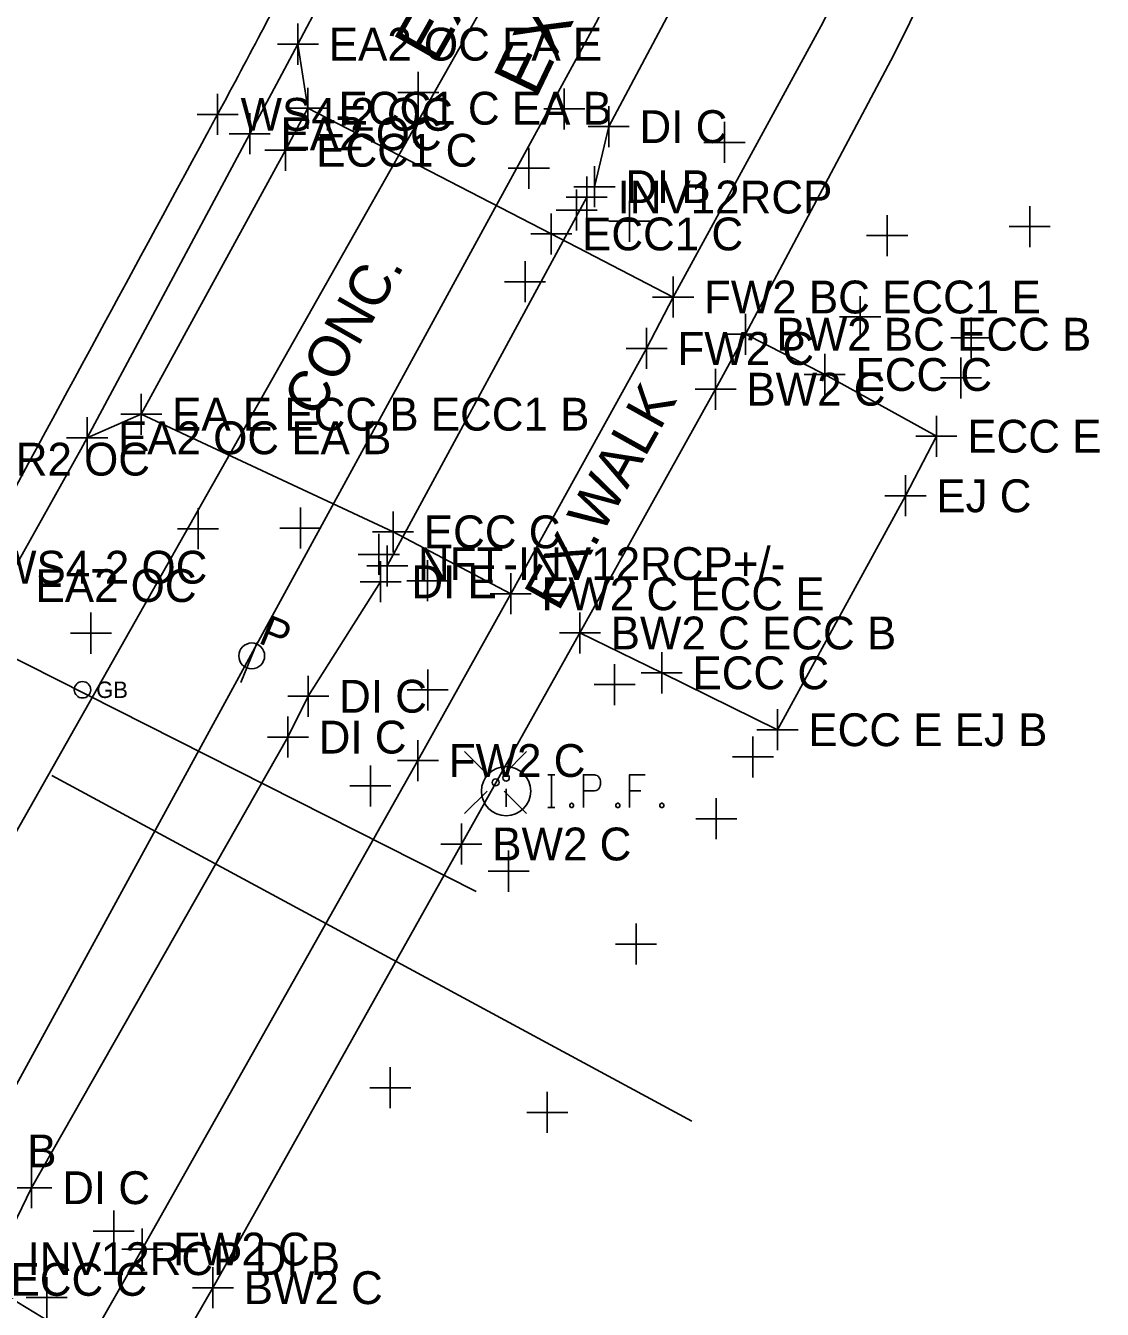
# Model space of a CAD drawing. Extents: x 1363693 to 1365209, y 422201 to 424153.
# Drawn here: x 1364183.9 to 1364236.4, y 422835.7 to 422898.3 of the extents above; entities that cross this region are included whole.
import ezdxf

# ---------------------------------------------------------------- set-up
doc = ezdxf.new("R2010")
doc.units = 0
for name, color, linetype in [('DR_X_Ditch', 7, 'Continuous'), ('DR_X_Storm_Sewer', 7, 'Continuous'), ('O-ALGN-TEXT-BASELINE-WERK-CL-RW', 7, 'Continuous'), ('OWNERS', 7, 'Continuous'), ('PM_X_Channelizing_Line', 7, 'Continuous'), ('PM_X_Edge_Line', 7, 'Continuous'), ('PV_X_Driveway', 7, 'Continuous'), ('PV_X_Joint', 7, 'Continuous'), ('RD_X_Text', 7, 'Continuous'), ('SV_X_Control_Cells_Found', 7, 'Continuous'), ('SV_X_Mon_Cells_Found', 7, 'Continuous'), ('SV_X_Original_Ground', 7, 'Continuous'), ('SV_X_Random_Point', 7, 'Continuous'), ('SV_X_Shot_Marker', 7, 'Continuous'), ('UT_X_Gas', 7, 'Continuous'), ('UT_X_Gas_Cells', 7, 'Continuous'), ('UT_X_Gas_Text', 7, 'Continuous'), ('UT_X_Sanitary_Line', 7, 'Continuous'), ('UT_X_Sanitary_Text', 7, 'Continuous'), ('UT_X_Unknown_Cells', 7, 'Continuous'), ('UT_X_Water', 7, 'Continuous'), ('UT_X_Water_Text', 7, 'Continuous')]:
    doc.layers.add(name, color=color, linetype=linetype)

msp = doc.modelspace()

# ---------------------------------------------------------------- linework, layer by layer
at = {"layer": 'DR_X_Ditch'}
for p, q in [((1364212.331, 422893.379), (1364220.841, 422909.378)), ((1364212.331, 422893.379), (1364220.841, 422909.378)), ((1364211.64, 422890.45), (1364212.331, 422893.379)), ((1364211.64, 422890.45), (1364212.331, 422893.379)), ((1364197.699, 422865.619), (1364201.219, 422871.2)), ((1364197.699, 422865.619), (1364201.219, 422871.2)), ((1364196.704, 422863.628), (1364197.699, 422865.619)), ((1364196.704, 422863.628), (1364197.699, 422865.619)), ((1364184.213, 422841.671), (1364196.704, 422863.628)), ((1364184.213, 422841.671), (1364196.704, 422863.628)), ((1364182.525, 422838.212), (1364184.213, 422841.671)), ((1364182.525, 422838.212), (1364184.213, 422841.671))]:
    msp.add_line(p, q, dxfattribs=at)
at = {"layer": 'DR_X_Storm_Sewer'}
msp.add_line((1364201.542, 422871.97), (1364211.264, 422889.948), dxfattribs=at)
msp.add_line((1364201.542, 422871.97), (1364211.264, 422889.948), dxfattribs=at)
at = {"layer": 'O-ALGN-TEXT-BASELINE-WERK-CL-RW'}
for points in [[(1364164.964, 422795.393), (1364177.23, 422816.837), (1364178.2, 422818.563), (1364186.943, 422834.018), (1364189.612, 422838.68), (1364203.041, 422862.487), (1364207.558, 422870.615), (1364214.18, 422882.569), (1364215.472, 422885.076), (1364222.781, 422898.475), (1364222.781, 422898.475), (1364226.694, 422906.346), (1364226.694, 422906.346), (1364234.426, 422922.921), (1364234.426, 422922.921), (1364234.736, 422923.619), (1364234.736, 422923.619), (1364236.839, 422928.637)], [(1364106.881, 422684.697), (1364119.186, 422706.188), (1364124.526, 422715.531), (1364131.747, 422728.163), (1364132.791, 422730.069), (1364143.66, 422749.553), (1364152.461, 422765.008), (1364156.109, 422771.56), (1364160.497, 422779.388), (1364168.274, 422793.373), (1364180.613, 422814.721), (1364181.642, 422816.657), (1364190.312, 422832.027), (1364193.051, 422836.798), (1364205.158, 422858.42), (1364210.927, 422868.703), (1364217.538, 422880.583), (1364219, 422883.263), (1364226.216, 422896.876), (1364226.216, 422896.876), (1364230.124, 422904.765), (1364230.124, 422904.765), (1364238.068, 422921.555)]]:
    msp.add_lwpolyline(points, dxfattribs=at)
at = {"layer": 'OWNERS'}
for p, q in [((1364197.671, 422894.276), (1364197.195, 422897.398)), ((1364186.928, 422878.215), (1364189.562, 422879.366))]:
    msp.add_line(p, q, dxfattribs=at)
for points in [[(1364139.16, 422793.068), (1364146.3, 422805.509), (1364158.984, 422827.195), (1364162.097, 422827.35), (1364170.617, 422843.461), (1364169.375, 422845.537), (1364171.082, 422848.945), (1364177.735, 422861.55), (1364177.735, 422861.55), (1364182.909, 422871.012), (1364182.909, 422871.012), (1364186.616, 422877.647), (1364186.616, 422877.647), (1364186.928, 422878.215), (1364186.928, 422878.215), (1364190.13, 422884.197), (1364190.13, 422884.197), (1364194.847, 422893.032), (1364194.847, 422893.032), (1364196.148, 422895.451), (1364196.148, 422895.451), (1364197.195, 422897.398), (1364197.195, 422897.398), (1364198.38, 422899.656)], [(1364189.562, 422879.366), (1364196.584, 422892.227), (1364197.671, 422894.276), (1364209.534, 422888.149), (1364215.472, 422885.076)], [(1364189.562, 422879.366), (1364201.825, 422873.631), (1364207.558, 422870.615)], [(1364170.617, 422843.461), (1364181.694, 422837.203), (1364186.943, 422834.018)]]:
    msp.add_lwpolyline(points, dxfattribs=at)
at = {"layer": 'PM_X_Channelizing_Line'}
for centre, radius, start, end in [((1363775.109, 423118.968), 474.856, 331.71827, 332.88059), ((1363871.483, 423067.116), 365.419, 331.54621, 331.71827), ((1210460.441, 506202.417), 174854.461, 331.53833418, 331.54620004)]:
    msp.add_arc(centre, radius, start, end, dxfattribs=at)
at = {"layer": 'PM_X_Edge_Line'}
for centre, radius, start, end in [((1363775.109, 423118.968), 474.856, 331.71827, 332.88059), ((1363871.483, 423067.116), 365.419, 331.54621, 331.71827), ((1210460.441, 506202.417), 174854.461, 331.53833418, 331.54620004)]:
    msp.add_arc(centre, radius, start, end, dxfattribs=at)
at = {"layer": 'PV_X_Driveway'}
for points in [[(1364219, 422883.263), (1364222.852, 422881.301), (1364228.297, 422878.292)], [(1364210.927, 422868.703), (1364214.912, 422866.762), (1364220.553, 422863.989)]]:
    msp.add_lwpolyline(points, dxfattribs=at)
at = {"layer": 'PV_X_Joint'}
for p, q in [((1364226.788, 422875.389), (1364228.297, 422878.292)), ((1364220.553, 422863.989), (1364226.788, 422875.389))]:
    msp.add_line(p, q, dxfattribs=at)
at = {"layer": 'SV_X_Control_Cells_Found'}
for p, q in [((1364205.314, 422862.924), (1364206.407, 422861.831)), ((1364207.24, 422861.831), (1364208.332, 422862.924)), ((1364205.314, 422859.906), (1364206.407, 422860.999)), ((1364207.24, 422860.999), (1364208.332, 422859.906))]:
    msp.add_line(p, q, dxfattribs=at)
msp.add_circle((1364206.824, 422861.421), 0.17, dxfattribs=at)
at = {"layer": 'SV_X_Mon_Cells_Found'}
msp.add_line((1364207.331, 422861.11), (1364207.331, 422860.227), dxfattribs=at)
for points in [[(1364209.361, 422861.794), (1364209.714, 422861.794)], [(1364209.538, 422860.194), (1364209.538, 422861.794)], [(1364211.103, 422860.194), (1364211.103, 422861.794), (1364211.632, 422861.794), (1364211.687, 422861.781), (1364211.764, 422861.756), (1364211.798, 422861.731), (1364211.831, 422861.705), (1364211.875, 422861.642), (1364211.908, 422861.579), (1364211.93, 422861.479), (1364211.93, 422861.327), (1364211.919, 422861.277), (1364211.897, 422861.201), (1364211.853, 422861.113), (1364211.809, 422861.075), (1364211.776, 422861.05), (1364211.72, 422861.025), (1364211.632, 422861.013), (1364211.103, 422861.013)], [(1364214.112, 422861.794), (1364213.352, 422861.794), (1364213.352, 422860.194)], [(1364213.352, 422861.013), (1364213.892, 422861.013)], [(1364209.361, 422860.194), (1364209.714, 422860.194)], [(1364210.497, 422860.408), (1364210.552, 422860.408), (1364210.585, 422860.383), (1364210.618, 422860.332), (1364210.618, 422860.269), (1364210.585, 422860.219), (1364210.552, 422860.194), (1364210.497, 422860.194), (1364210.464, 422860.219), (1364210.431, 422860.269), (1364210.431, 422860.332), (1364210.464, 422860.383), (1364210.497, 422860.408)], [(1364212.746, 422860.408), (1364212.801, 422860.408), (1364212.834, 422860.383), (1364212.867, 422860.332), (1364212.867, 422860.269), (1364212.834, 422860.219), (1364212.801, 422860.194), (1364212.746, 422860.194), (1364212.712, 422860.219), (1364212.679, 422860.269), (1364212.679, 422860.332), (1364212.712, 422860.383), (1364212.746, 422860.408)], [(1364214.895, 422860.408), (1364214.95, 422860.408), (1364214.983, 422860.383), (1364215.016, 422860.332), (1364215.016, 422860.269), (1364214.983, 422860.219), (1364214.95, 422860.194), (1364214.895, 422860.194), (1364214.862, 422860.219), (1364214.829, 422860.269), (1364214.829, 422860.332), (1364214.862, 422860.383), (1364214.895, 422860.408)]]:
    msp.add_lwpolyline(points, dxfattribs=at)
for centre, radius in [((1364207.331, 422860.994), 1.2), ((1364207.331, 422861.645), 0.16)]:
    msp.add_circle(centre, radius, dxfattribs=at)
at = {"layer": 'SV_X_Original_Ground'}
for p, q in [((1364203.055, 422894.048), (1364203.055, 422896.048)), ((1364193.281, 422892.978), (1364193.281, 422894.978)), ((1364202.055, 422895.048), (1364204.055, 422895.048)), ((1364210.164, 422893.244), (1364210.164, 422895.244)), ((1364192.281, 422893.978), (1364194.281, 422893.978)), ((1364209.164, 422894.244), (1364211.164, 422894.244)), ((1364217.971, 422891.614), (1364217.971, 422893.614)), ((1364216.971, 422892.614), (1364218.971, 422892.614)), ((1364208.441, 422890.354), (1364208.441, 422892.354)), ((1364207.441, 422891.354), (1364209.441, 422891.354)), ((1364210.77, 422888.311), (1364210.77, 422890.311)), ((1364209.77, 422889.311), (1364211.77, 422889.311)), ((1364213.342, 422887.77), (1364213.342, 422889.77)), ((1364232.843, 422887.505), (1364232.843, 422889.505)), ((1364212.342, 422888.77), (1364214.342, 422888.77)), ((1364225.896, 422887.066), (1364225.896, 422889.066)), ((1364224.896, 422888.066), (1364226.896, 422888.066)), ((1364231.843, 422888.505), (1364233.843, 422888.505)), ((1364208.258, 422884.824), (1364208.258, 422886.824)), ((1364207.258, 422885.824), (1364209.258, 422885.824)), ((1364224.581, 422883.111), (1364224.581, 422885.111)), ((1364223.581, 422884.111), (1364225.581, 422884.111)), ((1364229.991, 422882.079), (1364229.991, 422884.079)), ((1364228.991, 422883.079), (1364230.991, 422883.079)), ((1364229.489, 422880.133), (1364229.489, 422882.133)), ((1364228.489, 422881.133), (1364230.489, 422881.133)), ((1364192.329, 422872.785), (1364192.329, 422874.785)), ((1364197.316, 422872.815), (1364197.316, 422874.815)), ((1364191.329, 422873.785), (1364193.329, 422873.785)), ((1364196.316, 422873.815), (1364198.316, 422873.815)), ((1364201.134, 422871.53), (1364201.134, 422873.53)), ((1364200.134, 422872.53), (1364202.134, 422872.53)), ((1364203.502, 422870.253), (1364203.502, 422872.253)), ((1364202.502, 422871.253), (1364204.502, 422871.253)), ((1364187.111, 422867.695), (1364187.111, 422869.695)), ((1364186.111, 422868.695), (1364188.111, 422868.695)), ((1364203.515, 422864.93), (1364203.515, 422866.93)), ((1364212.62, 422865.189), (1364212.62, 422867.189)), ((1364211.62, 422866.189), (1364213.62, 422866.189)), ((1364202.515, 422865.93), (1364204.515, 422865.93)), ((1364219.355, 422861.661), (1364219.355, 422863.661)), ((1364218.355, 422862.661), (1364220.355, 422862.661)), ((1364200.726, 422860.248), (1364200.726, 422862.248)), ((1364199.726, 422861.248), (1364201.726, 422861.248)), ((1364217.57, 422858.649), (1364217.57, 422860.649)), ((1364216.57, 422859.649), (1364218.57, 422859.649)), ((1364207.458, 422856.096), (1364207.458, 422858.096)), ((1364206.458, 422857.096), (1364208.458, 422857.096)), ((1364213.667, 422852.546), (1364213.667, 422854.546)), ((1364212.667, 422853.546), (1364214.667, 422853.546)), ((1364201.694, 422845.545), (1364201.694, 422847.545)), ((1364200.694, 422846.545), (1364202.694, 422846.545)), ((1364209.341, 422844.343), (1364209.341, 422846.343)), ((1364208.341, 422845.343), (1364210.341, 422845.343)), ((1364188.221, 422838.552), (1364188.221, 422840.552)), ((1364187.221, 422839.552), (1364189.221, 422839.552)), ((1364184.956, 422835.318), (1364184.956, 422837.318)), ((1364183.956, 422836.318), (1364185.956, 422836.318))]:
    msp.add_line(p, q, dxfattribs=at)
at = {"layer": 'SV_X_Random_Point'}
for p, q in [((1364201.542, 422870.97), (1364201.542, 422872.97)), ((1364200.542, 422871.97), (1364202.542, 422871.97))]:
    msp.add_line(p, q, dxfattribs=at)
at = {"layer": 'SV_X_Shot_Marker'}
for p, q in [((1364197.195, 422896.398), (1364197.195, 422898.398)), ((1364196.195, 422897.398), (1364198.195, 422897.398)), ((1364197.671, 422893.276), (1364197.671, 422895.276)), ((1364212.331, 422892.379), (1364212.331, 422894.379)), ((1364194.847, 422892.032), (1364194.847, 422894.032)), ((1364196.671, 422894.276), (1364198.671, 422894.276)), ((1364196.584, 422891.227), (1364196.584, 422893.227)), ((1364211.331, 422893.379), (1364213.331, 422893.379)), ((1364193.847, 422893.032), (1364195.847, 422893.032)), ((1364195.584, 422892.227), (1364197.584, 422892.227)), ((1364211.64, 422889.45), (1364211.64, 422891.45)), ((1364211.264, 422888.948), (1364211.264, 422890.948)), ((1364210.264, 422889.948), (1364212.264, 422889.948)), ((1364210.64, 422890.45), (1364212.64, 422890.45)), ((1364209.534, 422887.149), (1364209.534, 422889.149)), ((1364208.534, 422888.149), (1364210.534, 422888.149)), ((1364215.472, 422884.076), (1364215.472, 422886.076)), ((1364214.472, 422885.076), (1364216.472, 422885.076)), ((1364219, 422882.263), (1364219, 422884.263)), ((1364214.18, 422881.569), (1364214.18, 422883.569)), ((1364218, 422883.263), (1364220, 422883.263)), ((1364213.18, 422882.569), (1364215.18, 422882.569)), ((1364222.852, 422880.301), (1364222.852, 422882.301)), ((1364217.538, 422879.583), (1364217.538, 422881.583)), ((1364221.852, 422881.301), (1364223.852, 422881.301)), ((1364216.538, 422880.583), (1364218.538, 422880.583)), ((1364189.562, 422878.366), (1364189.562, 422880.366)), ((1364188.562, 422879.366), (1364190.562, 422879.366)), ((1364186.928, 422877.215), (1364186.928, 422879.215)), ((1364228.297, 422877.292), (1364228.297, 422879.292)), ((1364185.928, 422878.215), (1364187.928, 422878.215)), ((1364227.297, 422878.292), (1364229.297, 422878.292)), ((1364226.788, 422874.389), (1364226.788, 422876.389)), ((1364225.788, 422875.389), (1364227.788, 422875.389)), ((1364201.825, 422872.631), (1364201.825, 422874.631)), ((1364200.825, 422873.631), (1364202.825, 422873.631)), ((1364201.219, 422870.2), (1364201.219, 422872.2)), ((1364200.219, 422871.2), (1364202.219, 422871.2)), ((1364207.558, 422869.615), (1364207.558, 422871.615)), ((1364206.558, 422870.615), (1364208.558, 422870.615)), ((1364210.927, 422867.703), (1364210.927, 422869.703)), ((1364209.927, 422868.703), (1364211.927, 422868.703)), ((1364214.912, 422865.762), (1364214.912, 422867.762)), ((1364197.699, 422864.619), (1364197.699, 422866.619)), ((1364213.912, 422866.762), (1364215.912, 422866.762)), ((1364196.699, 422865.619), (1364198.699, 422865.619)), ((1364220.553, 422862.989), (1364220.553, 422864.989)), ((1364196.704, 422862.628), (1364196.704, 422864.628)), ((1364219.553, 422863.989), (1364221.553, 422863.989)), ((1364195.704, 422863.628), (1364197.704, 422863.628)), ((1364203.041, 422861.487), (1364203.041, 422863.487)), ((1364202.041, 422862.487), (1364204.041, 422862.487)), ((1364205.158, 422857.42), (1364205.158, 422859.42)), ((1364204.158, 422858.42), (1364206.158, 422858.42)), ((1364184.213, 422840.671), (1364184.213, 422842.671)), ((1364183.213, 422841.671), (1364185.213, 422841.671)), ((1364189.612, 422837.68), (1364189.612, 422839.68)), ((1364188.612, 422838.68), (1364190.612, 422838.68)), ((1364193.051, 422835.798), (1364193.051, 422837.798)), ((1364192.051, 422836.798), (1364194.051, 422836.798))]:
    msp.add_line(p, q, dxfattribs=at)
at = {"layer": 'UT_X_Gas'}
msp.add_line((1364205.869, 422856.111), (1364147.056, 422885.823), dxfattribs=at)
at = {"layer": 'UT_X_Gas_Cells'}
msp.add_circle((1364186.699, 422865.936), 0.4, dxfattribs=at)
at = {"layer": 'UT_X_Sanitary_Line'}
msp.add_line((1364185.201, 422861.753), (1364216.389, 422844.918), dxfattribs=at)
msp.add_lwpolyline([(1364014.261, 422733.758), (1364095.069, 422702.67), (1364258.083, 422991.019), (1364292.624, 423022.755)], dxfattribs=at)
at = {"layer": 'UT_X_Unknown_Cells'}
msp.add_line((1364194.408, 422866.292), (1364195.211, 422868.237), dxfattribs=at)
msp.add_circle((1364194.942, 422867.586), 0.63, dxfattribs=at)
at = {"layer": 'UT_X_Water'}
msp.add_lwpolyline([(1364263.889, 423134.469), (1364270.338, 423133.178), (1364266, 423070.885), (1364241.238, 422967.415), (1364211.801, 422898.599), (1364139.416, 422765.962), (1364094.46, 422690.2)], dxfattribs=at)

# ---------------------------------------------------------------- texts
at = {"layer": 'RD_X_Text'}
for s, rotation, p in [('CONC.', 60.281, (1364198.127, 422879.123)), ('EX.WALK', 60.80754, (1364209.889, 422869.702))]:
    msp.add_text(s, height=2, rotation=rotation, dxfattribs=at).set_placement(p)
at = {"layer": 'SV_X_Original_Ground'}
for s, p in [('WS4-2 OC', (1364194.4, 422893.178)), ('WS8 OC CR2 OC', (1364172.87, 422876.374)), ('WS4-2 OC', (1364182.44, 422871.108))]:
    msp.add_text(s, height=1.6, dxfattribs=at).set_placement(p)
at = {"layer": 'SV_X_Random_Point'}
msp.add_text('NFT-INV12RCP+/-', height=1.6, dxfattribs=at).set_placement((1364203.042, 422871.284))
at = {"layer": 'SV_X_Shot_Marker'}
for s, p in [('EA2 OC EA E', (1364198.695, 422896.598)), ('ECC1 C EA B', (1364199.171, 422893.476)), ('EA2 OC', (1364196.347, 422892.232)), ('DI C', (1364213.831, 422892.579)), ('ECC1 C', (1364198.084, 422891.427)), ('DI B', (1364213.14, 422889.65)), ('INV12RCP', (1364212.764, 422889.148)), ('ECC1 C', (1364211.034, 422887.349)), ('FW2 BC ECC1 E', (1364216.972, 422884.276)), ('BW2 BC ECC B', (1364220.5, 422882.463)), ('FW2 C', (1364215.68, 422881.769)), ('ECC C', (1364224.352, 422880.501)), ('BW2 C', (1364219.038, 422879.783)), ('EA E ECC B ECC1 B', (1364191.062, 422878.566)), ('EA2 OC EA B', (1364188.428, 422877.415)), ('ECC E EJ E', (1364229.797, 422877.492)), ('EJ C', (1364228.288, 422874.589)), ('ECC C', (1364203.325, 422872.831)), ('EA2 OC', (1364184.409, 422870.212)), ('DI E', (1364202.719, 422870.4)), ('FW2 C ECC E', (1364209.058, 422869.815)), ('BW2 C ECC B', (1364212.427, 422867.903)), ('ECC C', (1364216.412, 422865.962)), ('DI C', (1364199.199, 422864.819)), ('DI C', (1364198.204, 422862.828)), ('ECC E EJ B', (1364222.053, 422863.189)), ('FW2 C', (1364204.541, 422861.687)), ('BW2 C', (1364206.658, 422857.62)), ('EA2 C ECC B', (1364172.117, 422842.661)), ('DI C', (1364185.713, 422840.871)), ('FW2 C', (1364191.112, 422837.88)), ('INV12RCP DI B', (1364184.025, 422837.412)), ('ECC C', (1364183.194, 422836.403)), ('BW2 C', (1364194.551, 422835.998))]:
    msp.add_text(s, height=1.6, dxfattribs=at).set_placement(p)
at = {"layer": 'UT_X_Gas_Text'}
msp.add_text('GB', height=0.8, dxfattribs=at).set_placement((1364187.367, 422865.536))
at = {"layer": 'UT_X_Sanitary_Text'}
msp.add_text('EX. 12" SAN.', height=2.4, rotation=60.44536, dxfattribs=at).set_placement((1364203.878, 422896.362))
at = {"layer": 'UT_X_Unknown_Cells'}
msp.add_text('P', height=1.503, rotation=337.58271, dxfattribs=at).set_placement((1364195.211, 422868.237))
at = {"layer": 'UT_X_Water_Text'}
msp.add_text('EX. 8" WM', height=2.4, rotation=64.42645, dxfattribs=at).set_placement((1364208.816, 422894.736))

doc.saveas('drawing.dxf')
